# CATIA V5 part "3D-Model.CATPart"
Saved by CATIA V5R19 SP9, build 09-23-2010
Part number: 140604_Spirale
Bounding box of the stored display mesh (mm): x -45 to 45, y -44.99 to 44.99, z -20 to 0
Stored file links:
  C:\Users\schwarz_maximilian\Desktop\Spirale\3D-Model.CATPart
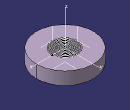
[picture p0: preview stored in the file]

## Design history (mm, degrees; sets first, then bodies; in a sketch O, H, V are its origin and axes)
Parameters
  Durchmesser = 90 mm
  Staercke_Platte = 20 mm
  `Durchmesser_Fräser` = 1 mm
  `Tiefe_Fräser` = 3 mm
  Steigung_Spirale = 2 mm
  Umdrehungen_Spirale = 10
AxisSystem1: origin (0, 0, 0), X (1, 0, 0), Y (0, 1, 0), Z (0, 0, 1)
Set1
  Spiral1: Center vertex [YZ plane of AxisSystem1 | ZX plane of AxisSystem1 | XY plane of AxisSystem1], Direction edge [XY plane of AxisSystem1 | ZX plane of AxisSystem1], Support XY plane of AxisSystem1, Radius 0, Revolutions 10 {= Umdrehungen_Spirale}, Angle 0, Pitch 2 {= Steigung_Spirale}
  Sketch1 "SK_Scheibe" on XY plane of AxisSystem1, origin (0, 0, 0), H (1, 0, 0), V (0, 1, 0)
    circle A1 centre (0, 0) radius 45
    radius A1 = 45 {= Durchmesser /2}
  Intersect1: ToIntersect1 Spiral1, ToIntersect2 YZ plane of AxisSystem1
  Extract1: ExtractElem vertex of Intersect1
  Split1: ToCut Spiral1, Cutting Extract1
  CurvePar1: Offset Spiral1, Offset2 0, Offset1 0.5 {= `Durchmesser_Fräser` /2}
  CurvePar2: Offset Spiral1, Offset2 0, Offset1 -0.5 {= -`Durchmesser_Fräser` /2}
  Circle1: type CtrRad, Start 90, End 360, Radius 0.5 {= `Durchmesser_Fräser` /2}, Center vertex [YZ plane of AxisSystem1 | ZX plane of AxisSystem1 | XY plane of AxisSystem1], Support XY plane of AxisSystem1, FirstDirection (1, 0, 0)
  Circle2: type CtrRad, Start -45, End 245, Radius 0.5 {= `Durchmesser_Fräser` /2}, Center vertex of Spiral1, Support XY plane of AxisSystem1, FirstDirection (1, 0, 0)
  Extrude1: Lim1 3, Lim2 0, Direction XY plane of AxisSystem1, Element1 Circle1
  Extrude2: Lim1 3, Lim2 0, Direction XY plane of AxisSystem1, Element1 CurvePar2
  Extrude3: Lim1 3, Lim2 0, Direction XY plane of AxisSystem1, Element1 CurvePar1
  Intersect2: ToIntersect1 Extrude1, ToIntersect2 Extrude2
  Split2: ToCut Extrude1, Cutting Intersect2
  Split3: ToCut Split2, Cutting Extrude3
  Extrude4: Lim1 3, Lim2 0, Direction XY plane of AxisSystem1, Element1 Circle2
  Intersect3: ToIntersect1 Extrude4, ToIntersect2 Extrude2
  Split4: ToCut Extrude4, Cutting Intersect3
  Intersect4: ToIntersect1 Split4, ToIntersect2 Extrude3
  Split5: ToCut Split4, Cutting Intersect4
  Join1: Elements (Split5; Extrude2; Extrude3; Split3)
  Boundary1: Boundary edge of Extrude2
  Fill1: Boundary Boundary1
  Join2: Elements (Join1; Fill1)
Body1 (main body)
  Pad1: profile Sketch1, direction (0, 0, -1), length 20 {= Staercke_Platte}
  Split6: SplitPlane Join2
